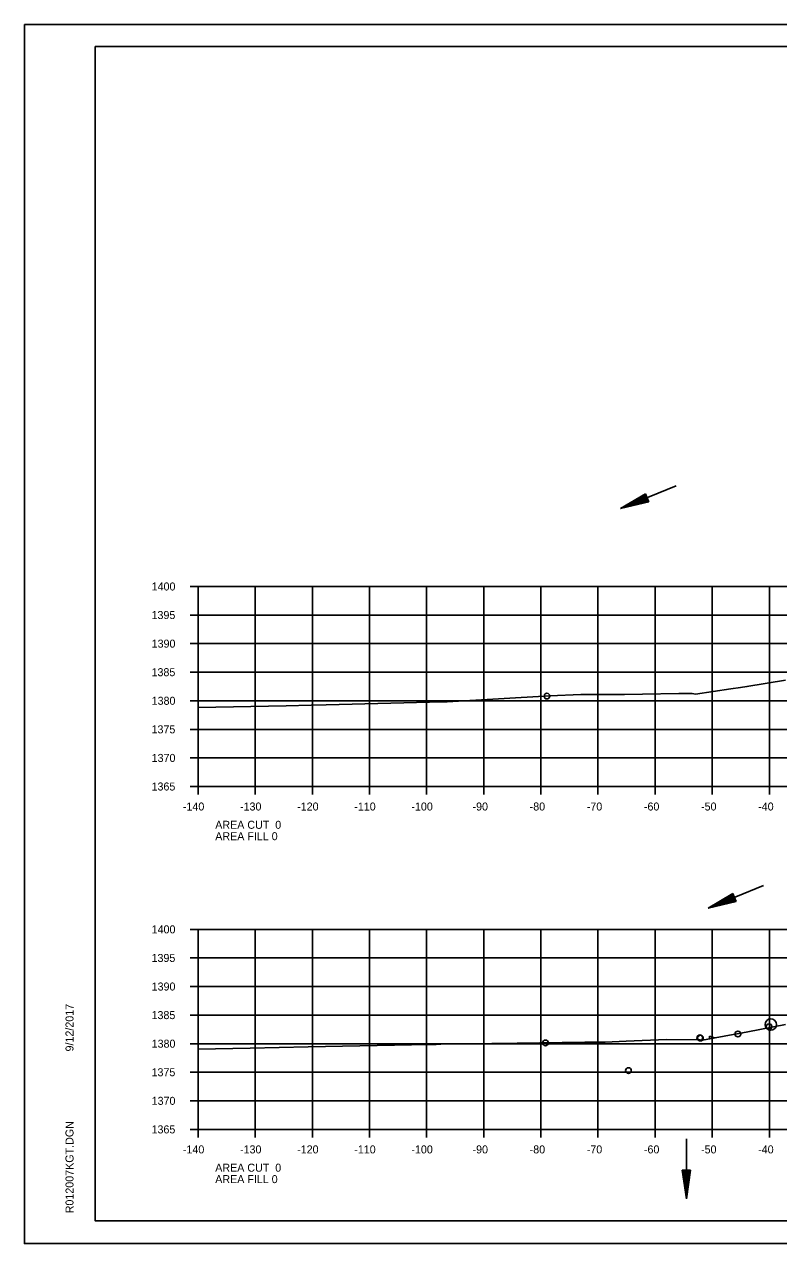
# Model space of a CAD drawing. Extents: x 1374311 to 1383814, y 384102 to 406278.
# Drawn here: x 1381458.2 to 1381590.3, y 384751.3 to 384964.6 of the extents above; entities that cross this region are included whole.
import ezdxf

# ---------------------------------------------------------------- set-up
doc = ezdxf.new("R2010")
doc.units = 0
for name, color, linetype in [('R_Axis', 7, 'Continuous'), ('R_Axis Annot', 7, 'Continuous'), ('R_Border', 7, 'Continuous'), ('R_Draft', 7, 'Continuous'), ('R_Exist Surface', 7, 'Continuous'), ('R_Grid', 7, 'Continuous'), ('R_No Plot', 7, 'Continuous'), ('R_Water', 7, 'Continuous')]:
    doc.layers.add(name, color=color, linetype=linetype)

msp = doc.modelspace()

# ---------------------------------------------------------------- linework, layer by layer
at = {"layer": 'R_Axis'}
for p, q in [((1381487.26, 384866.26), (1381488.66, 384866.26)), ((1381488.66, 384831.26), (1381488.66, 384866.26)), ((1381487.26, 384861.26), (1381488.66, 384861.26)), ((1381487.26, 384856.26), (1381488.66, 384856.26)), ((1381487.26, 384851.26), (1381488.66, 384851.26)), ((1381487.26, 384846.26), (1381488.66, 384846.26)), ((1381487.26, 384841.26), (1381488.66, 384841.26)), ((1381487.26, 384836.26), (1381488.66, 384836.26)), ((1381487.26, 384831.26), (1381488.66, 384831.26)), ((1381488.66, 384831.26), (1381768.66, 384831.26)), ((1381488.66, 384829.86), (1381488.66, 384831.26)), ((1381498.66, 384829.86), (1381498.66, 384831.26)), ((1381508.66, 384829.86), (1381508.66, 384831.26)), ((1381518.66, 384829.86), (1381518.66, 384831.26)), ((1381528.66, 384829.86), (1381528.66, 384831.26)), ((1381538.66, 384829.86), (1381538.66, 384831.26)), ((1381548.66, 384829.86), (1381548.66, 384831.26)), ((1381558.66, 384829.86), (1381558.66, 384831.26)), ((1381568.66, 384829.86), (1381568.66, 384831.26)), ((1381578.66, 384829.86), (1381578.66, 384831.26)), ((1381588.66, 384829.86), (1381588.66, 384831.26)), ((1381487.26, 384806.26), (1381488.66, 384806.26)), ((1381488.66, 384771.26), (1381488.66, 384806.26)), ((1381487.26, 384801.26), (1381488.66, 384801.26)), ((1381487.26, 384796.26), (1381488.66, 384796.26)), ((1381487.26, 384791.26), (1381488.66, 384791.26)), ((1381487.26, 384786.26), (1381488.66, 384786.26)), ((1381487.26, 384781.26), (1381488.66, 384781.26)), ((1381487.26, 384776.26), (1381488.66, 384776.26)), ((1381487.26, 384771.26), (1381488.66, 384771.26)), ((1381488.66, 384771.26), (1381768.66, 384771.26)), ((1381488.66, 384769.86), (1381488.66, 384771.26)), ((1381498.66, 384769.86), (1381498.66, 384771.26)), ((1381508.66, 384769.86), (1381508.66, 384771.26)), ((1381518.66, 384769.86), (1381518.66, 384771.26)), ((1381528.66, 384769.86), (1381528.66, 384771.26)), ((1381538.66, 384769.86), (1381538.66, 384771.26)), ((1381548.66, 384769.86), (1381548.66, 384771.26)), ((1381558.66, 384769.86), (1381558.66, 384771.26)), ((1381568.66, 384769.86), (1381568.66, 384771.26)), ((1381578.66, 384769.86), (1381578.66, 384771.26)), ((1381588.66, 384769.86), (1381588.66, 384771.26))]:
    msp.add_line(p, q, dxfattribs=at)
at = {"layer": 'R_Border'}
for p, q in [((1381470.66, 384960.72), (1381786.84, 384960.72)), ((1381470.66, 384755.26), (1381470.66, 384960.72)), ((1381470.66, 384755.26), (1381470.66, 384755.26)), ((1381786.84, 384755.26), (1381470.66, 384755.26))]:
    msp.add_line(p, q, dxfattribs=at)
at = {"layer": 'R_Draft'}
for p, q in [((1381566.97, 384882.48), (1381562.63, 384879.89)), ((1381567.02, 384882.37), (1381563.4, 384880.21)), ((1381567.54, 384881.09), (1381566.97, 384882.48)), ((1381567.54, 384881.09), (1381562.63, 384879.89)), ((1381567.5, 384881.21), (1381563.4, 384880.21)), ((1381567.07, 384882.25), (1381564.2, 384880.54)), ((1381567.45, 384881.33), (1381564.2, 384880.54)), ((1381567.12, 384882.13), (1381564.97, 384880.85)), ((1381567.4, 384881.44), (1381564.97, 384880.85)), ((1381567.17, 384882.01), (1381565.75, 384881.17)), ((1381567.35, 384881.56), (1381565.75, 384881.17)), ((1381567.21, 384881.9), (1381566.53, 384881.49)), ((1381567.3, 384881.68), (1381566.53, 384881.49)), ((1381582.28, 384812.55), (1381577.94, 384809.96)), ((1381582.33, 384812.44), (1381578.71, 384810.28)), ((1381582.38, 384812.32), (1381579.51, 384810.6)), ((1381582.43, 384812.2), (1381580.28, 384810.92)), ((1381582.48, 384812.08), (1381581.06, 384811.24)), ((1381582.52, 384811.97), (1381581.84, 384811.56)), ((1381582.85, 384811.16), (1381582.28, 384812.55)), ((1381582.85, 384811.16), (1381577.94, 384809.96)), ((1381582.8, 384811.28), (1381578.71, 384810.28)), ((1381582.76, 384811.4), (1381579.51, 384810.6)), ((1381582.71, 384811.51), (1381580.28, 384810.92)), ((1381582.66, 384811.63), (1381581.06, 384811.24)), ((1381582.61, 384811.75), (1381581.84, 384811.56)), ((1381573.38, 384764.11), (1381574.13, 384759.11)), ((1381574.88, 384764.11), (1381573.38, 384764.11)), ((1381573.5, 384764.11), (1381574.13, 384759.95)), ((1381573.63, 384764.11), (1381574.13, 384760.81)), ((1381573.76, 384764.11), (1381574.13, 384761.64)), ((1381573.88, 384764.11), (1381574.13, 384762.49)), ((1381574.01, 384764.11), (1381574.13, 384763.32)), ((1381574.88, 384764.11), (1381574.13, 384759.11)), ((1381574.37, 384764.11), (1381574.13, 384762.49)), ((1381574.63, 384764.11), (1381574.13, 384760.81)), ((1381574.75, 384764.11), (1381574.13, 384759.95)), ((1381574.5, 384764.11), (1381574.13, 384761.64)), ((1381574.25, 384764.11), (1381574.13, 384763.32))]:
    msp.add_line(p, q, dxfattribs=at)
at = {"layer": 'R_Exist Surface'}
for points in [[(1381488.66, 384845.1), (1381504.09, 384845.39), (1381508.45, 384845.49), (1381511.09, 384845.55), (1381531.44, 384846.06), (1381532.27, 384846.1), (1381550.25, 384847.11), (1381555.65, 384847.35), (1381563.31, 384847.38), (1381566.44, 384847.44), (1381572.79, 384847.52), (1381574.02, 384847.54), (1381575.12, 384847.53), (1381575.75, 384847.44), (1381581.93, 384848.33), (1381583.61, 384848.57), (1381584.73, 384848.74), (1381591.49, 384849.87)], [(1381488.66, 384785.3), (1381497.78, 384785.47), (1381507.94, 384785.69), (1381529.05, 384786.11), (1381530.32, 384786.13), (1381531.17, 384786.16), (1381544.49, 384786.33), (1381556.35, 384786.5), (1381559.9, 384786.55), (1381563.58, 384786.68), (1381570.63, 384787.01), (1381576.54, 384786.91), (1381576.93, 384786.9), (1381582.99, 384787.96), (1381583.96, 384788.14), (1381584.91, 384788.33), (1381591.46, 384789.6)]]:
    msp.add_lwpolyline(points, dxfattribs=at)
at = {"layer": 'R_Grid'}
for p, q in [((1381488.66, 384866.26), (1381768.66, 384866.26)), ((1381488.66, 384831.26), (1381488.66, 384866.26)), ((1381498.66, 384831.26), (1381498.66, 384866.26)), ((1381508.66, 384831.26), (1381508.66, 384866.26)), ((1381518.66, 384831.26), (1381518.66, 384866.26)), ((1381528.66, 384831.26), (1381528.66, 384866.26)), ((1381538.66, 384831.26), (1381538.66, 384866.26)), ((1381548.66, 384831.26), (1381548.66, 384866.26)), ((1381558.66, 384831.26), (1381558.66, 384866.26)), ((1381568.66, 384831.26), (1381568.66, 384866.26)), ((1381578.66, 384831.26), (1381578.66, 384866.26)), ((1381588.66, 384831.26), (1381588.66, 384866.26)), ((1381488.66, 384861.26), (1381768.66, 384861.26)), ((1381488.66, 384856.26), (1381768.66, 384856.26)), ((1381488.66, 384851.26), (1381768.66, 384851.26)), ((1381488.66, 384846.26), (1381768.66, 384846.26)), ((1381488.66, 384841.26), (1381768.66, 384841.26)), ((1381488.66, 384836.26), (1381768.66, 384836.26)), ((1381488.66, 384831.26), (1381768.66, 384831.26)), ((1381488.66, 384806.26), (1381768.66, 384806.26)), ((1381488.66, 384771.26), (1381488.66, 384806.26)), ((1381498.66, 384771.26), (1381498.66, 384806.26)), ((1381508.66, 384771.26), (1381508.66, 384806.26)), ((1381518.66, 384771.26), (1381518.66, 384806.26)), ((1381528.66, 384771.26), (1381528.66, 384806.26)), ((1381538.66, 384771.26), (1381538.66, 384806.26)), ((1381548.66, 384771.26), (1381548.66, 384806.26)), ((1381558.66, 384771.26), (1381558.66, 384806.26)), ((1381568.66, 384771.26), (1381568.66, 384806.26)), ((1381578.66, 384771.26), (1381578.66, 384806.26)), ((1381588.66, 384771.26), (1381588.66, 384806.26)), ((1381488.66, 384801.26), (1381768.66, 384801.26)), ((1381488.66, 384796.26), (1381768.66, 384796.26)), ((1381488.66, 384791.26), (1381768.66, 384791.26)), ((1381488.66, 384786.26), (1381768.66, 384786.26)), ((1381488.66, 384781.26), (1381768.66, 384781.26)), ((1381488.66, 384776.26), (1381768.66, 384776.26)), ((1381488.66, 384771.26), (1381768.66, 384771.26))]:
    msp.add_line(p, q, dxfattribs=at)
at = {"layer": 'R_No Plot'}
for p, q in [((1381458.26, 384964.61), (1381791.59, 384964.61)), ((1381458.26, 384751.28), (1381791.59, 384751.28))]:
    msp.add_line(p, q, dxfattribs=at)
for points in [[(1381458.25, 384964.61), (1381791.59, 384964.61), (1381791.59, 384751.28), (1381458.25, 384751.28)], [(1381704.58, 384960.72), (1381704.58, 384950.84), (1381740.31, 384950.84), (1381740.31, 384947.92), (1381763.51, 384947.92), (1381763.51, 384924.7), (1381786.84, 384924.7), (1381786.84, 384755.26), (1381470.66, 384755.26), (1381470.66, 384960.72)], [(1381578.18, 384787.57), (1381578.18, 384787.12), (1381579.06, 384787.28)]]:
    msp.add_lwpolyline(points, close=True, dxfattribs=at)
for centre, radius in [((1381549.73, 384847.08), 0.5), ((1381588.9, 384789.6), 1), ((1381588.6, 384789.24), 0.5), ((1381549.46, 384786.4), 0.5), ((1381576.49, 384787.28), 0.5), ((1381576.6, 384787.24), 0.5), ((1381583.16, 384787.95), 0.5), ((1381563.99, 384781.56), 0.5)]:
    msp.add_circle(centre, radius, dxfattribs=at)
at = {"layer": 'R_Water'}
for p, q in [((1381572.35, 384883.87), (1381562.63, 384879.89)), ((1381587.66, 384813.94), (1381577.94, 384809.96)), ((1381574.13, 384769.62), (1381574.13, 384759.11))]:
    msp.add_line(p, q, dxfattribs=at)

# ---------------------------------------------------------------- texts
at = {"layer": 'R_Axis Annot'}
for s, p in [('1400', (1381480.53, 384865.56)), ('1395', (1381480.51, 384860.56)), ('1390', (1381480.53, 384855.56)), ('1385', (1381480.51, 384850.56)), ('1380', (1381480.53, 384845.56)), ('1375', (1381480.51, 384840.56)), ('1370', (1381480.53, 384835.56)), ('1365', (1381480.51, 384830.56)), ('-140', (1381486, 384827.06)), ('-130', (1381496, 384827.06)), ('-120', (1381506, 384827.06)), ('-110', (1381516, 384827.06)), ('-100', (1381526, 384827.06)), ('-90', (1381536.7, 384827.06)), ('-80', (1381546.7, 384827.06)), ('-70', (1381556.7, 384827.06)), ('-60', (1381566.7, 384827.06)), ('-50', (1381576.7, 384827.06)), ('-40', (1381586.7, 384827.06)), ('AREA CUT  0', (1381491.66, 384823.86)), ('AREA FILL 0', (1381491.66, 384821.86)), ('1400', (1381480.53, 384805.56)), ('1395', (1381480.51, 384800.56)), ('1390', (1381480.53, 384795.56)), ('1385', (1381480.51, 384790.56)), ('1380', (1381480.53, 384785.56)), ('1375', (1381480.51, 384780.56)), ('1370', (1381480.53, 384775.56)), ('1365', (1381480.51, 384770.56)), ('-140', (1381486, 384767.06)), ('-130', (1381496, 384767.06)), ('-120', (1381506, 384767.06)), ('-110', (1381516, 384767.06)), ('-100', (1381526, 384767.06)), ('-90', (1381536.7, 384767.06)), ('-80', (1381546.7, 384767.06)), ('-70', (1381556.7, 384767.06)), ('-60', (1381566.7, 384767.06)), ('-50', (1381576.7, 384767.06)), ('-40', (1381586.7, 384767.06)), ('AREA CUT  0', (1381491.66, 384763.86)), ('AREA FILL 0', (1381491.66, 384761.86))]:
    msp.add_text(s, height=1.4, dxfattribs=at).set_placement(p)
at = {"layer": 'R_Border'}
for s, p in [('9/12/2017', (1381466.85, 384784.9)), ('R012007KGT.DGN', (1381466.85, 384756.58))]:
    msp.add_text(s, height=1.4, rotation=90, dxfattribs=at).set_placement(p)

doc.saveas('drawing.dxf')
